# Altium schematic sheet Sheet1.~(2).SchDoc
size B; SheetNumber: 1; SheetTotal: 1
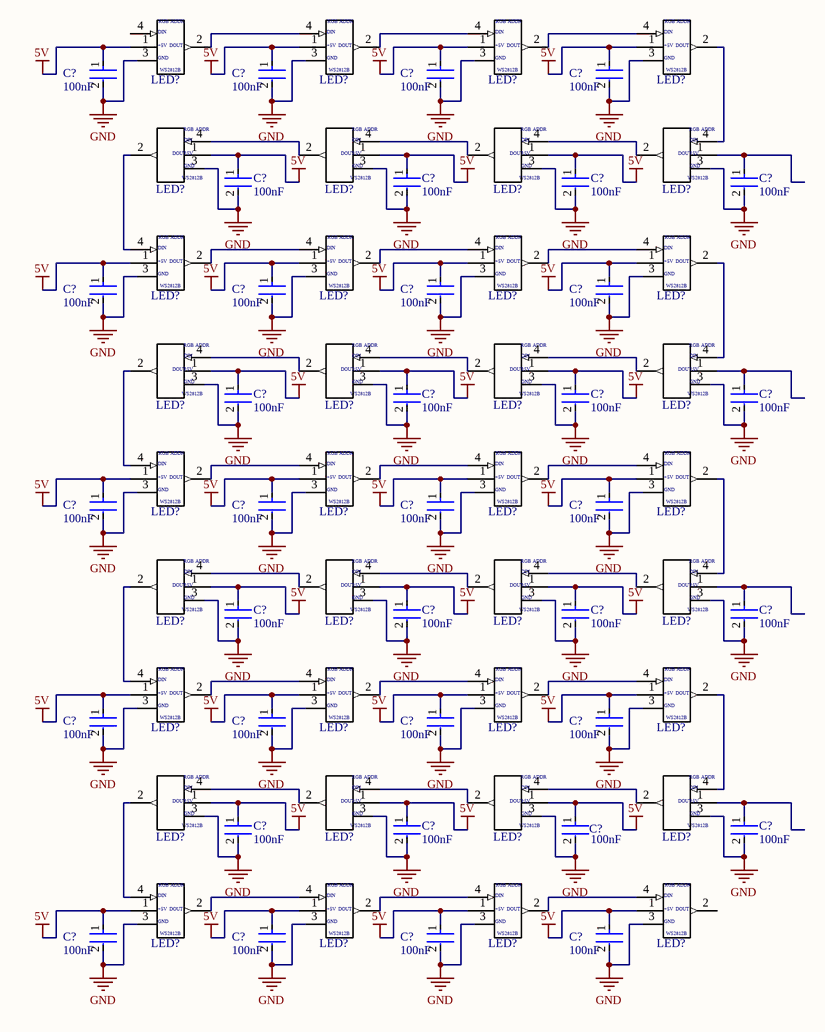
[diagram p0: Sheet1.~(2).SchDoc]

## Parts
(Parts that share a designator on the sheet are numbered #1, #2 ... from top to bottom, then left to right.)
C?#1  100nF  [FP-CC0603-DA-IPC_B]
C?#2  100nF  [FP-CC0603-DA-IPC_B]
C?#3  100nF  [FP-CC0603-DA-IPC_B]
C?#4  100nF  [FP-CC0603-DA-IPC_B]
C?#5  100nF  [FP-CC0603-DA-IPC_B]
C?#6  100nF  [FP-CC0603-DA-IPC_B]
C?#7  100nF  [FP-CC0603-DA-IPC_B]
C?#8  100nF  [FP-CC0603-DA-IPC_B]
C?#9  100nF  [FP-CC0603-DA-IPC_B]
C?#10  100nF  [FP-CC0603-DA-IPC_B]
C?#11  100nF  [FP-CC0603-DA-IPC_B]
C?#12  100nF  [FP-CC0603-DA-IPC_B]
C?#13  100nF  [FP-CC0603-DA-IPC_B]
C?#14  100nF  [FP-CC0603-DA-IPC_B]
C?#15  100nF  [FP-CC0603-DA-IPC_B]
C?#16  100nF  [FP-CC0603-DA-IPC_B]
C?#17  100nF  [FP-CC0603-DA-IPC_B]
C?#18  100nF  [FP-CC0603-DA-IPC_B]
C?#19  100nF  [FP-CC0603-DA-IPC_B]
C?#20  100nF  [FP-CC0603-DA-IPC_B]
C?#21  100nF  [FP-CC0603-DA-IPC_B]
C?#22  100nF  [FP-CC0603-DA-IPC_B]
C?#23  100nF  [FP-CC0603-DA-IPC_B]
C?#24  100nF  [FP-CC0603-DA-IPC_B]
C?#25  100nF  [FP-CC0603-DA-IPC_B]
C?#26  100nF  [FP-CC0603-DA-IPC_B]
C?#27  100nF  [FP-CC0603-DA-IPC_B]
C?#28  100nF  [FP-CC0603-DA-IPC_B]
C?#29  100nF  [FP-CC0603-DA-IPC_B]
C?#30  100nF  [FP-CC0603-DA-IPC_B]
C?#31  100nF  [FP-CC0603-DA-IPC_B]
C?#32  100nF  [FP-CC0603-DA-IPC_B]
C?#33  100nF  [FP-CC0603-DA-IPC_B]
C?#34  100nF  [FP-CC0603-DA-IPC_B]
C?#35  100nF  [FP-CC0603-DA-IPC_B]
C?#36  100nF  [FP-CC0603-DA-IPC_B]
LED?#1  WS2812B  [*WS2812B_WS2812B(Primary)]  (value not drawn)
LED?#2  WS2812B  [*WS2812B_WS2812B(Primary)]  (value not drawn)
LED?#3  WS2812B  [*WS2812B_WS2812B(Primary)]  (value not drawn)
LED?#4  WS2812B  [*WS2812B_WS2812B(Primary)]  (value not drawn)
LED?#5  WS2812B  [*WS2812B_WS2812B(Primary)]  (value not drawn)
LED?#6  WS2812B  [*WS2812B_WS2812B(Primary)]  (value not drawn)
LED?#7  WS2812B  [*WS2812B_WS2812B(Primary)]  (value not drawn)
LED?#8  WS2812B  [*WS2812B_WS2812B(Primary)]  (value not drawn)
LED?#9  WS2812B  [*WS2812B_WS2812B(Primary)]  (value not drawn)
LED?#10  WS2812B  [*WS2812B_WS2812B(Primary)]  (value not drawn)
LED?#11  WS2812B  [*WS2812B_WS2812B(Primary)]  (value not drawn)
LED?#12  WS2812B  [*WS2812B_WS2812B(Primary)]  (value not drawn)
LED?#13  WS2812B  [*WS2812B_WS2812B(Primary)]  (value not drawn)
LED?#14  WS2812B  [*WS2812B_WS2812B(Primary)]  (value not drawn)
LED?#15  WS2812B  [*WS2812B_WS2812B(Primary)]  (value not drawn)
LED?#16  WS2812B  [*WS2812B_WS2812B(Primary)]  (value not drawn)
LED?#17  WS2812B  [*WS2812B_WS2812B(Primary)]  (value not drawn)
LED?#18  WS2812B  [*WS2812B_WS2812B(Primary)]  (value not drawn)
LED?#19  WS2812B  [*WS2812B_WS2812B(Primary)]  (value not drawn)
LED?#20  WS2812B  [*WS2812B_WS2812B(Primary)]  (value not drawn)
LED?#21  WS2812B  [*WS2812B_WS2812B(Primary)]  (value not drawn)
LED?#22  WS2812B  [*WS2812B_WS2812B(Primary)]  (value not drawn)
LED?#23  WS2812B  [*WS2812B_WS2812B(Primary)]  (value not drawn)
LED?#24  WS2812B  [*WS2812B_WS2812B(Primary)]  (value not drawn)
LED?#25  WS2812B  [*WS2812B_WS2812B(Primary)]  (value not drawn)
LED?#26  WS2812B  [*WS2812B_WS2812B(Primary)]  (value not drawn)
LED?#27  WS2812B  [*WS2812B_WS2812B(Primary)]  (value not drawn)
LED?#28  WS2812B  [*WS2812B_WS2812B(Primary)]  (value not drawn)
LED?#29  WS2812B  [*WS2812B_WS2812B(Primary)]  (value not drawn)
LED?#30  WS2812B  [*WS2812B_WS2812B(Primary)]  (value not drawn)
LED?#31  WS2812B  [*WS2812B_WS2812B(Primary)]  (value not drawn)
LED?#32  WS2812B  [*WS2812B_WS2812B(Primary)]  (value not drawn)
LED?#33  WS2812B  [*WS2812B_WS2812B(Primary)]  (value not drawn)
LED?#34  WS2812B  [*WS2812B_WS2812B(Primary)]  (value not drawn)
LED?#35  WS2812B  [*WS2812B_WS2812B(Primary)]  (value not drawn)
LED?#36  WS2812B  [*WS2812B_WS2812B(Primary)]  (value not drawn)

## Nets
5V: C?#1.1 C?#2.1 C?#3.1 C?#4.1 C?#5.1 C?#6.1 C?#7.1 C?#9.1 C?#10.1 C?#11.1 C?#12.1 C?#13.1 C?#14.1 C?#15.1 C?#17.1 C?#18.1 C?#19.1 C?#20.1 C?#21.1 C?#22.1 C?#23.1 C?#25.1 C?#26.1 C?#27.1 C?#28.1 C?#29.1 C?#30.1 C?#31.1 C?#33.1 C?#34.1 C?#35.1 C?#36.1
GND: C?#1.2 C?#2.2 C?#3.2 C?#4.2 C?#5.2 C?#6.2 C?#7.2 C?#8.2 C?#9.2 C?#10.2 C?#11.2 C?#12.2 C?#13.2 C?#14.2 C?#15.2 C?#16.2 C?#17.2 C?#18.2 C?#19.2 C?#20.2 C?#21.2 C?#22.2 C?#23.2 C?#24.2 C?#25.2 C?#26.2 C?#27.2 C?#28.2 C?#29.2 C?#30.2 C?#31.2 C?#32.2 C?#33.2 C?#34.2 C?#35.2 C?#36.2
NetLED?#1_2: LED?#1.2(DO) LED?#2.4
NetLED?#2_2: LED?#2.2(DO) LED?#3.4
NetLED?#3_2: LED?#3.2(DO) LED?#4.4
NetLED?#4_2: LED?#4.2(DO) LED?#8.4
NetLED?#5_2: LED?#5.2(DO) LED?#9.4
NetLED?#5_4: LED?#5.4 LED?#6.2(DO)
NetLED?#6_4: LED?#6.4 LED?#7.2(DO)
NetLED?#7_4: LED?#7.4 LED?#8.2(DO)
NetLED?#9_2: LED?#9.2(DO) LED?#10.4
NetLED?#10_2: LED?#10.2(DO) LED?#11.4
NetLED?#11_2: LED?#11.2(DO) LED?#12.4
NetLED?#12_2: LED?#12.2(DO) LED?#16.4
NetLED?#13_2: LED?#13.2(DO) LED?#17.4
NetLED?#13_4: LED?#13.4 LED?#14.2(DO)
NetLED?#14_4: LED?#14.4 LED?#15.2(DO)
NetLED?#15_4: LED?#15.4 LED?#16.2(DO)
NetLED?#17_2: LED?#17.2(DO) LED?#18.4
NetLED?#18_2: LED?#18.2(DO) LED?#19.4
NetLED?#19_2: LED?#19.2(DO) LED?#20.4
NetLED?#20_2: LED?#20.2(DO) LED?#24.4
NetLED?#21_2: LED?#21.2(DO) LED?#25.4
NetLED?#21_4: LED?#21.4 LED?#22.2(DO)
NetLED?#22_4: LED?#22.4 LED?#23.2(DO)
NetLED?#23_4: LED?#23.4 LED?#24.2(DO)
NetLED?#25_2: LED?#25.2(DO) LED?#26.4
NetLED?#26_2: LED?#26.2(DO) LED?#27.4
NetLED?#27_2: LED?#27.2(DO) LED?#28.4
NetLED?#28_2: LED?#28.2(DO) LED?#32.4
NetLED?#29_2: LED?#29.2(DO) LED?#33.4
NetLED?#29_4: LED?#29.4 LED?#30.2(DO)
NetLED?#30_4: LED?#30.4 LED?#31.2(DO)
NetLED?#31_4: LED?#31.4 LED?#32.2(DO)
NetLED?#33_2: LED?#33.2(DO) LED?#34.4
NetLED?#34_2: LED?#34.2(DO) LED?#35.4
NetLED?#35_2: LED?#35.2(DO) LED?#36.4

Not connected (* = marked no-connect by the designer): C?#8 1; C?#16 1; C?#24 1; C?#32 1; LED?#1 1 3 4; LED?#2 1 3; LED?#3 1 3; LED?#4 1 3; LED?#5 1 3; LED?#6 1 3; LED?#7 1 3; LED?#8 1 3; LED?#9 1 3; LED?#10 1 3; LED?#11 1 3; LED?#12 1 3; LED?#13 1 3; LED?#14 1 3; LED?#15 1 3; LED?#16 1 3; LED?#17 1 3; LED?#18 1 3; LED?#19 1 3; LED?#20 1 3; LED?#21 1 3; LED?#22 1 3; LED?#23 1 3; LED?#24 1 3; LED?#25 1 3; LED?#26 1 3; LED?#27 1 3; LED?#28 1 3; LED?#29 1 3; LED?#30 1 3; LED?#31 1 3; LED?#32 1 3; LED?#33 1 3; LED?#34 1 3; LED?#35 1 3; LED?#36 1 2(DO) 3

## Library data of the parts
C?#1-C?#36 = CMP-03422-001228-1: CAP CER 0.1UF 10V X7R 0603; Manufacturer Part Number: CC0603KRX7R6BB104; Manufacturer: YAGEO; Material: Ceramic; Tolerance: 0.1; Temperature Coefficient: 15%
LED?#1-LED?#36 = WS2812B: Intelligent control LED integrated light source; MF: Worldsemi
